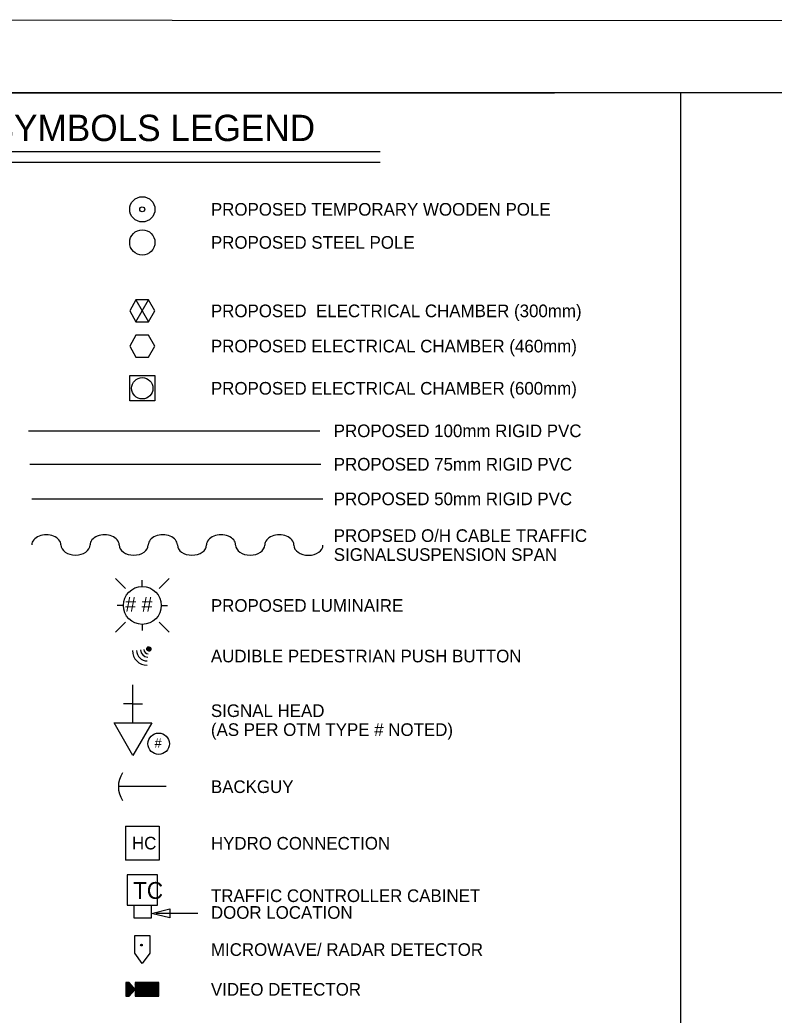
# Model space of a CAD drawing. Extents: x 595568 to 603392, y 4837996 to 4846579.
# Drawn here: x 603080.76 to 603106.66, y 4846502.21 to 4846536.38 of the extents above; entities that cross this region are included whole.
import ezdxf

# ---------------------------------------------------------------- set-up
doc = ezdxf.new("R2010")
doc.units = 0
for name, color, linetype in [('-PRINT HALFSIZE', 7, 'Continuous'), ('ENG_BORDER', 7, 'Continuous'), ('TCS_100mm-NEW', 7, 'Continuous'), ('TCS_50mm-NEW', 7, 'Continuous'), ('TCS_75mm-NEW', 7, 'Continuous'), ('TCS_BACKGUY', 7, 'Continuous'), ('TCS_CONTROLLER', 7, 'Continuous'), ('TCS_ELEC-CHAMBER-NEW', 7, 'Continuous'), ('TCS_HYDROSUPPLY', 7, 'Continuous'), ('TCS_LEGEND', 7, 'Continuous'), ('TCS_LUMINAIRE-NEW', 7, 'Continuous'), ('TCS_POLE-NEW', 7, 'Continuous'), ('TCS_PUSHBUTTON', 7, 'Continuous'), ('TCS_RADAR', 7, 'Continuous'), ('TCS_SIGNALHEAD', 7, 'Continuous'), ('TCS_SPAN-NEW', 7, 'Continuous'), ('TCS_VIDEO', 7, 'Continuous')]:
    doc.layers.add(name, color=color, linetype=linetype)

msp = doc.modelspace()

# ---------------------------------------------------------------- linework, layer by layer
at = {"layer": '-PRINT HALFSIZE'}
msp.add_lwpolyline([(603056.659, 4846536.385), (603261.877, 4846536.304), (603261.821, 4846396.201), (603056.604, 4846396.282)], close=True, dxfattribs=at)
at = {"layer": 'ENG_BORDER'}
msp.add_line((603103.463, 4846399.391), (603103.462, 4846533.885), dxfattribs=at)
msp.add_lwpolyline([(603258.618, 4846533.885), (603059.791, 4846533.885)], dxfattribs=at)
at = {"layer": 'TCS_100mm-NEW'}
msp.add_line((603081.058, 4846522.272), (603091.058, 4846522.272), dxfattribs=at)
at = {"layer": 'TCS_50mm-NEW'}
msp.add_line((603081.168, 4846519.94), (603091.168, 4846519.94), dxfattribs=at)
at = {"layer": 'TCS_75mm-NEW'}
msp.add_line((603081.095, 4846521.128), (603091.095, 4846521.128), dxfattribs=at)
at = {"layer": 'TCS_BACKGUY'}
msp.add_line((603084.141, 4846510.064), (603085.783, 4846510.064), dxfattribs=at)
msp.add_arc((603084.99, 4846510.051), 0.849, 145.8914, 214.1086, dxfattribs=at)
at = {"layer": 'TCS_CONTROLLER'}
for p, q in [((603084.442, 4846507.028), (603084.442, 4846505.987)), ((603085.483, 4846507.028), (603084.442, 4846507.028)), ((603085.483, 4846505.987), (603085.483, 4846507.028)), ((603084.442, 4846505.987), (603085.483, 4846505.987)), ((603084.666, 4846505.983), (603084.666, 4846505.549)), ((603085.274, 4846505.549), (603085.274, 4846505.983)), ((603084.666, 4846505.549), (603085.274, 4846505.549)), ((603086.869, 4846505.701), (603085.433, 4846505.701))]:
    msp.add_line(p, q, dxfattribs=at)
msp.add_lwpolyline([(603085.274, 4846505.701), (603085.912, 4846505.861), (603085.912, 4846505.542), (603085.912, 4846505.542)], close=True, dxfattribs=at)
at = {"layer": 'TCS_ELEC-CHAMBER-NEW'}
for p, q in [((603084.745, 4846526.767), (603084.529, 4846526.392)), ((603084.745, 4846526.767), (603085.179, 4846526.016)), ((603084.745, 4846526.016), (603085.179, 4846526.767)), ((603085.179, 4846526.767), (603084.745, 4846526.767)), ((603085.396, 4846526.392), (603085.179, 4846526.767)), ((603084.529, 4846526.392), (603084.745, 4846526.016)), ((603085.179, 4846526.016), (603085.396, 4846526.392)), ((603084.745, 4846526.016), (603085.179, 4846526.016)), ((603084.745, 4846525.559), (603084.529, 4846525.183)), ((603085.179, 4846525.559), (603084.745, 4846525.559)), ((603085.396, 4846525.183), (603085.179, 4846525.559)), ((603084.529, 4846525.183), (603084.745, 4846524.807)), ((603085.179, 4846524.807), (603085.396, 4846525.183)), ((603084.745, 4846524.807), (603085.179, 4846524.807)), ((603084.529, 4846523.299), (603084.529, 4846524.167)), ((603084.529, 4846524.167), (603085.396, 4846524.167)), ((603085.396, 4846524.167), (603085.396, 4846523.299)), ((603085.396, 4846523.299), (603084.529, 4846523.299))]:
    msp.add_line(p, q, dxfattribs=at)
msp.add_circle((603084.962, 4846523.733), 0.367, dxfattribs=at)
at = {"layer": 'TCS_HYDROSUPPLY'}
for p, q in [((603084.385, 4846508.693), (603084.385, 4846507.524)), ((603084.385, 4846508.693), (603085.54, 4846508.693)), ((603085.54, 4846508.693), (603085.54, 4846507.524)), ((603085.54, 4846507.524), (603084.385, 4846507.524))]:
    msp.add_line(p, q, dxfattribs=at)
at = {"layer": 'TCS_LEGEND'}
for p, q in [((603070.116, 4846531.862), (603093.137, 4846531.862)), ((603070.116, 4846531.499), (603093.137, 4846531.499))]:
    msp.add_line(p, q, dxfattribs=at)
msp.add_lwpolyline([(603064.132, 4846533.885), (603099.121, 4846533.885)], dxfattribs=at)
at = {"layer": 'TCS_LUMINAIRE-NEW'}
for p, q in [((603084.387, 4846516.852), (603084.042, 4846517.197)), ((603084.962, 4846516.928), (603084.962, 4846517.145)), ((603085.537, 4846516.852), (603085.882, 4846517.197)), ((603084.311, 4846516.277), (603084.095, 4846516.277)), ((603085.613, 4846516.277), (603085.83, 4846516.277)), ((603084.387, 4846515.702), (603084.042, 4846515.357)), ((603085.537, 4846515.702), (603085.882, 4846515.357)), ((603084.962, 4846515.627), (603084.962, 4846515.41))]:
    msp.add_line(p, q, dxfattribs=at)
msp.add_circle((603084.962, 4846516.277), 0.651, dxfattribs=at)
at = {"layer": 'TCS_POLE-NEW'}
for centre, radius in [((603084.962, 4846529.879), 0.434), ((603084.962, 4846529.879), 0.0867), ((603084.962, 4846528.743), 0.434)]:
    msp.add_circle(centre, radius, dxfattribs=at)
at = {"layer": 'TCS_PUSHBUTTON'}
for p, q in [((603085.114, 4846514.778), (603085.189, 4846514.854)), ((603085.114, 4846514.769), (603085.198, 4846514.853)), ((603085.114, 4846514.789), (603085.178, 4846514.853)), ((603085.116, 4846514.761), (603085.207, 4846514.851)), ((603085.117, 4846514.802), (603085.165, 4846514.85)), ((603085.119, 4846514.753), (603085.214, 4846514.848)), ((603085.122, 4846514.746), (603085.221, 4846514.845)), ((603085.126, 4846514.74), (603085.228, 4846514.841)), ((603085.127, 4846514.822), (603085.145, 4846514.84)), ((603085.13, 4846514.734), (603085.233, 4846514.837)), ((603085.135, 4846514.728), (603085.239, 4846514.832)), ((603085.141, 4846514.724), (603085.244, 4846514.827)), ((603085.146, 4846514.719), (603085.248, 4846514.821)), ((603085.153, 4846514.715), (603085.252, 4846514.814)), ((603085.16, 4846514.712), (603085.255, 4846514.807)), ((603085.168, 4846514.71), (603085.258, 4846514.8)), ((603085.176, 4846514.708), (603085.259, 4846514.791)), ((603085.185, 4846514.707), (603085.26, 4846514.782)), ((603085.196, 4846514.708), (603085.26, 4846514.771)), ((603085.209, 4846514.71), (603085.257, 4846514.758)), ((603085.23, 4846514.721), (603085.246, 4846514.737))]:
    msp.add_line(p, q, dxfattribs=at)
msp.add_circle((603085.187, 4846514.78), 0.0733, dxfattribs=at)
for centre, radius, start, end in [((603085.128, 4846514.729), 0.506, 180, 270), ((603085.128, 4846514.729), 0.361, 180, 270), ((603085.153, 4846514.757), 0.253, 181.8853, 269.2012), ((603085.165, 4846514.757), 0.145, 180, 270)]:
    msp.add_arc(centre, radius, start, end, dxfattribs=at)
at = {"layer": 'TCS_RADAR'}
msp.add_lwpolyline([(603084.705, 4846504.939), (603085.219, 4846504.939), (603085.219, 4846504.335), (603084.955, 4846503.976), (603084.705, 4846504.335)], close=True, dxfattribs=at)
for centre, radius in [((603084.933, 4846504.61), 0.0279), ((603084.936, 4846504.61), 0.0254), ((603084.938, 4846504.607), 0.0231), ((603084.94, 4846504.607), 0.021), ((603084.94, 4846504.607), 0.021), ((603084.942, 4846504.607), 0.0191)]:
    msp.add_circle(centre, radius, dxfattribs=at)
at = {"layer": 'TCS_SIGNALHEAD'}
for p, q in [((603084.641, 4846512.249), (603084.641, 4846513.55)), ((603084.641, 4846512.899), (603084.316, 4846512.899)), ((603084.641, 4846512.899), (603084.967, 4846512.899)), ((603084.641, 4846511.122), (603083.991, 4846512.249)), ((603083.991, 4846512.249), (603085.292, 4846512.249)), ((603085.292, 4846512.249), (603084.641, 4846511.122))]:
    msp.add_line(p, q, dxfattribs=at)
msp.add_circle((603085.524, 4846511.525), 0.368, dxfattribs=at)
at = {"layer": 'TCS_SPAN-NEW'}
for centre, start_param, end_param in [((603081.667, 4846518.354), 0, 3.141593), ((603083.667, 4846518.353), 0, 3.141593), ((603085.667, 4846518.352), 6.283185, 9.424778), ((603087.667, 4846518.352), 6.283185, 9.424778), ((603089.667, 4846518.351), 0, 3.141593), ((603082.667, 4846518.354), 3.141593, 6.283185), ((603084.667, 4846518.353), 3.141593, 6.283185), ((603086.667, 4846518.352), 3.141593, 6.283185), ((603088.667, 4846518.351), 3.141593, 6.283185), ((603090.667, 4846518.35), 3.141593, 6.283185)]:
    msp.add_ellipse(centre, major_axis=(0.5, 0), ratio=0.7, start_param=start_param, end_param=end_param, dxfattribs=at)
at = {"layer": 'TCS_VIDEO'}
for p, q in [((603084.514, 4846503.326), (603084.396, 4846503.326)), ((603084.396, 4846503.326), (603084.396, 4846503.091)), ((603084.396, 4846503.217), (603084.505, 4846503.326)), ((603084.396, 4846503.237), (603084.485, 4846503.326)), ((603084.396, 4846503.258), (603084.464, 4846503.326)), ((603084.396, 4846503.278), (603084.444, 4846503.326)), ((603084.396, 4846503.299), (603084.423, 4846503.326)), ((603084.396, 4846503.319), (603084.403, 4846503.326)), ((603084.396, 4846503.196), (603084.519, 4846503.319)), ((603084.396, 4846503.176), (603084.529, 4846503.308)), ((603084.396, 4846503.156), (603084.538, 4846503.297)), ((603084.396, 4846503.135), (603084.547, 4846503.286)), ((603084.396, 4846503.115), (603084.557, 4846503.275)), ((603084.396, 4846503.094), (603084.566, 4846503.264)), ((603084.396, 4846503.074), (603084.576, 4846503.253)), ((603084.396, 4846503.053), (603084.585, 4846503.242)), ((603084.396, 4846503.033), (603084.595, 4846503.231)), ((603084.396, 4846503.012), (603084.604, 4846503.22)), ((603084.396, 4846502.992), (603084.614, 4846503.209)), ((603084.396, 4846502.971), (603084.623, 4846503.198)), ((603084.396, 4846502.951), (603084.632, 4846503.187)), ((603084.396, 4846502.931), (603084.642, 4846503.176)), ((603084.396, 4846502.91), (603084.651, 4846503.165)), ((603084.396, 4846502.89), (603084.661, 4846503.154)), ((603084.396, 4846502.869), (603084.67, 4846503.143)), ((603084.396, 4846503.091), (603084.396, 4846502.856)), ((603084.404, 4846502.856), (603084.68, 4846503.132)), ((603084.424, 4846502.856), (603084.689, 4846503.121)), ((603084.445, 4846502.856), (603084.699, 4846503.11)), ((603084.465, 4846502.856), (603084.708, 4846503.099)), ((603084.485, 4846502.856), (603084.684, 4846503.054)), ((603084.715, 4846503.091), (603084.514, 4846503.326)), ((603084.514, 4846502.856), (603084.715, 4846503.091)), ((603084.715, 4846502.872), (603085.169, 4846503.326)), ((603084.715, 4846502.892), (603085.149, 4846503.326)), ((603084.715, 4846502.913), (603085.128, 4846503.326)), ((603084.715, 4846502.933), (603085.108, 4846503.326)), ((603084.715, 4846502.953), (603085.087, 4846503.326)), ((603084.715, 4846502.974), (603085.067, 4846503.326)), ((603084.715, 4846502.994), (603085.046, 4846503.326)), ((603084.715, 4846503.015), (603085.026, 4846503.326)), ((603084.715, 4846503.035), (603085.006, 4846503.326)), ((603084.715, 4846503.056), (603084.985, 4846503.326)), ((603084.715, 4846503.076), (603084.965, 4846503.326)), ((603084.715, 4846503.097), (603084.944, 4846503.326)), ((603084.715, 4846503.117), (603084.924, 4846503.326)), ((603084.715, 4846503.137), (603084.903, 4846503.326)), ((603084.715, 4846503.158), (603084.883, 4846503.326)), ((603084.715, 4846503.178), (603084.862, 4846503.326)), ((603084.715, 4846503.199), (603084.842, 4846503.326)), ((603084.715, 4846503.219), (603084.822, 4846503.326)), ((603084.715, 4846503.24), (603084.801, 4846503.326)), ((603084.715, 4846503.26), (603084.781, 4846503.326)), ((603084.715, 4846503.281), (603084.76, 4846503.326)), ((603084.715, 4846503.301), (603084.74, 4846503.326)), ((603084.715, 4846503.321), (603084.719, 4846503.326)), ((603084.72, 4846502.856), (603085.19, 4846503.326)), ((603084.74, 4846502.856), (603085.21, 4846503.326)), ((603084.761, 4846502.856), (603085.23, 4846503.326)), ((603084.781, 4846502.856), (603085.251, 4846503.326)), ((603084.802, 4846502.856), (603085.271, 4846503.326)), ((603084.822, 4846502.856), (603085.292, 4846503.326)), ((603084.843, 4846502.856), (603085.312, 4846503.326)), ((603084.863, 4846502.856), (603085.333, 4846503.326)), ((603084.884, 4846502.856), (603085.353, 4846503.326)), ((603084.904, 4846502.856), (603085.374, 4846503.326)), ((603084.924, 4846502.856), (603085.394, 4846503.326)), ((603084.945, 4846502.856), (603085.414, 4846503.326)), ((603084.965, 4846502.856), (603085.435, 4846503.326)), ((603084.986, 4846502.856), (603085.455, 4846503.326)), ((603085.006, 4846502.856), (603085.476, 4846503.326)), ((603085.027, 4846502.856), (603085.496, 4846503.326)), ((603085.047, 4846502.856), (603085.517, 4846503.326)), ((603085.068, 4846502.856), (603085.528, 4846503.317)), ((603085.088, 4846502.856), (603085.528, 4846503.296)), ((603085.109, 4846502.856), (603085.528, 4846503.276)), ((603085.129, 4846502.856), (603085.528, 4846503.256)), ((603085.149, 4846502.856), (603085.528, 4846503.235)), ((603085.17, 4846502.856), (603085.528, 4846503.215)), ((603085.19, 4846502.856), (603085.528, 4846503.194)), ((603085.211, 4846502.856), (603085.528, 4846503.174)), ((603085.231, 4846502.856), (603085.528, 4846503.153)), ((603085.252, 4846502.856), (603085.528, 4846503.133)), ((603085.272, 4846502.856), (603085.528, 4846503.112)), ((603085.293, 4846502.856), (603085.528, 4846503.092)), ((603085.313, 4846502.856), (603085.528, 4846503.072)), ((603085.333, 4846502.856), (603085.528, 4846503.051)), ((603084.396, 4846502.856), (603084.514, 4846502.856)), ((603084.506, 4846502.856), (603084.56, 4846502.911)), ((603085.354, 4846502.856), (603085.528, 4846503.031)), ((603085.374, 4846502.856), (603085.528, 4846503.01)), ((603085.395, 4846502.856), (603085.528, 4846502.99)), ((603085.415, 4846502.856), (603085.528, 4846502.969)), ((603085.436, 4846502.856), (603085.528, 4846502.949)), ((603085.456, 4846502.856), (603085.528, 4846502.928)), ((603085.477, 4846502.856), (603085.528, 4846502.908)), ((603085.497, 4846502.856), (603085.528, 4846502.887)), ((603085.517, 4846502.856), (603085.528, 4846502.867))]:
    msp.add_line(p, q, dxfattribs=at)
msp.add_lwpolyline([(603084.715, 4846502.856), (603085.528, 4846502.856), (603085.528, 4846503.326), (603084.715, 4846503.326), (603084.715, 4846503.091), (603084.715, 4846502.856)], dxfattribs=at)

# ---------------------------------------------------------------- texts
at = {"layer": 'TCS_CONTROLLER'}
msp.add_text('TC', height=0.5783, dxfattribs=at).set_placement((603084.644, 4846506.198))
at = {"layer": 'TCS_HYDROSUPPLY'}
msp.add_text('HC', height=0.4337, dxfattribs=at).set_placement((603084.607, 4846507.897))
at = {"layer": 'TCS_LEGEND'}
for s, height, p in [('TRAFFIC SYMBOLS LEGEND', 0.90363, (603074.313, 4846532.224)), ('PROPOSED TEMPORARY WOODEN POLE', 0.43374, (603087.319, 4846529.662)), ('PROPOSED STEEL POLE', 0.43374, (603087.319, 4846528.526)), ('PROPOSED  ELECTRICAL CHAMBER (300mm)', 0.43374, (603087.319, 4846526.175)), ('PROPOSED ELECTRICAL CHAMBER (460mm)', 0.43374, (603087.319, 4846524.966)), ('PROPOSED ELECTRICAL CHAMBER (600mm)', 0.43374, (603087.319, 4846523.516)), ('PROPOSED 100mm RIGID PVC', 0.43374, (603091.538, 4846522.056)), ('PROPOSED 75mm RIGID PVC', 0.43374, (603091.538, 4846520.908)), ('PROPOSED 50mm RIGID PVC', 0.43374, (603091.538, 4846519.719)), ('PROPSED O/H CABLE TRAFFIC', 0.43374, (603091.538, 4846518.457)), ('SIGNALSUSPENSION SPAN', 0.43374, (603091.538, 4846517.806)), ('PROPOSED LUMINAIRE', 0.43374, (603087.318, 4846516.058)), ('AUDIBLE PEDESTRIAN PUSH BUTTON', 0.43374, (603087.319, 4846514.321)), ('SIGNAL HEAD ', 0.43374, (603087.319, 4846512.444)), ('(AS PER OTM TYPE # NOTED)', 0.43374, (603087.319, 4846511.794)), ('BACKGUY', 0.4337, (603087.319, 4846509.834)), ('HYDRO CONNECTION', 0.43374, (603087.319, 4846507.891)), ('TRAFFIC CONTROLLER CABINET', 0.43374, (603087.319, 4846506.09)), ('DOOR LOCATION', 0.43374, (603087.319, 4846505.515)), ('MICROWAVE/ RADAR DETECTOR', 0.43374, (603087.319, 4846504.241)), ('VIDEO DETECTOR', 0.43374, (603087.319, 4846502.874))]:
    msp.add_text(s, height=height, dxfattribs=at).set_placement(p)
at = {"layer": 'TCS_LUMINAIRE-NEW'}
msp.add_text('# #', height=0.506, dxfattribs=at).set_placement((603084.372, 4846516.062))
at = {"layer": 'TCS_SIGNALHEAD'}
msp.add_text('#', height=0.325, dxfattribs=at).set_placement((603085.382, 4846511.394))

doc.saveas('drawing.dxf')
